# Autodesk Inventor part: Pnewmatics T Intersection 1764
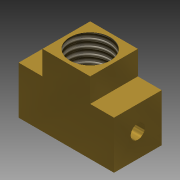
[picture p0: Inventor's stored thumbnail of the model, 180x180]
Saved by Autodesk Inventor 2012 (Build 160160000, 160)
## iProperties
Created: 2010-02
Part Number: Pnewmatics T Intersection 1764
Document SubType Name: Modeling
Designer: jgehrig
Density: 1 g/cm^3
Material: Default
Author: jgehrig
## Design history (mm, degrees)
sketch "Sketch1"
  geometry: L1 (-25.271, 28.178)-(-25.271, 21.828); L2 (-25.271, 21.828)-(-31.621, 21.828); L3 (-31.621, 21.828)-(-31.621, 9.128); L4 (-31.621, 9.128)-(-6.221, 9.128); L5 (-6.221, 9.128)-(-6.221, 21.828); L6 (-6.221, 21.828)-(-12.571, 21.828); L7 (-12.571, 21.828)-(-12.571, 28.178); L8 (-12.571, 28.178)-(-25.271, 28.178); 1 further point
  constraints: 16 end point, 4 parallel, 3 perpendicular, 1 vertical
  dimensions: "d0" = 25.4 distance of L3.end L4.end; "d1" = 6.35 distance of L1.end L2.end; "d2" = 12.7 distance of L7.end L1.start; "d3" = 6.35 distance of L6.end L7.end; "d4" = 12.7 distance of L4.end L5.end; "d5" = 12.7 distance of L2.end L3.end
extrude "Extrusion1" new body sketch "Sketch1" distance "d6" = 12.7; taper "d7" = 0 deg
sketch "Sketch2"
  geometry: C1 r 5.397 at (6.35, -6.35); 1 further point
  constraints: 1 centre point
  dimensions: "d8" = 10.795 diameter of C1
extrude "Extrusion2" cut sketch "Sketch2" distance "d9" = 16.51; taper "d10" = 0 deg
thread "Thread1" dims "d11" = 25.4, "d12" = 0
sketch "Sketch3"
  geometry: C1 r 1.905 at (-6.35, 6.35); 1 further point
  constraints: 1 centre point
  dimensions: "d13" = 3.81 diameter of C1
extrude "Extrusion3" cut sketch "Sketch3" stored distance "d14" = 16.51; taper "d15" = 0 deg
body "Solid1"
